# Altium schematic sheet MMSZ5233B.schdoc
size 127 x 101 mm
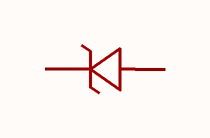
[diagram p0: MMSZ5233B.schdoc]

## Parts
D?  mmsz5233b  [SOD-123_L2.7-W1.6-LS3.7-RD]  (value not drawn)

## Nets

Not connected (* = marked no-connect by the designer): D? 1(K) 2(A)

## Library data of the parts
D? = mmsz5233b: 二极管配置:1个独立式;稳压值(标称值):6V;稳压值(范围):5.7V~6.3V;耗散功率(Pd):500mW;; Manufacturer: CJ(江苏长电/长晶); AddInBom: yes; ModelId: ad7e39f9e5534b3c96ffdc5532ebb493; ModelName: SOD-123_L2.7-W1.6-H1.4-LS3.7; ModelTransform: 146.026,62.992,0,180,0,0,0.0005,0,0; Diode Configuration: 1个独立式; Zener Voltage(Nom): 6V; Reverse Leakage Current (Ir): 5uA@3.5V; Pd - Power Dissipation: 500mW; Impedance(Zzt): 7Ω; Impedance(Zzk): 1.6kΩ; Operating Junction Temperature Range: -55℃~+150℃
